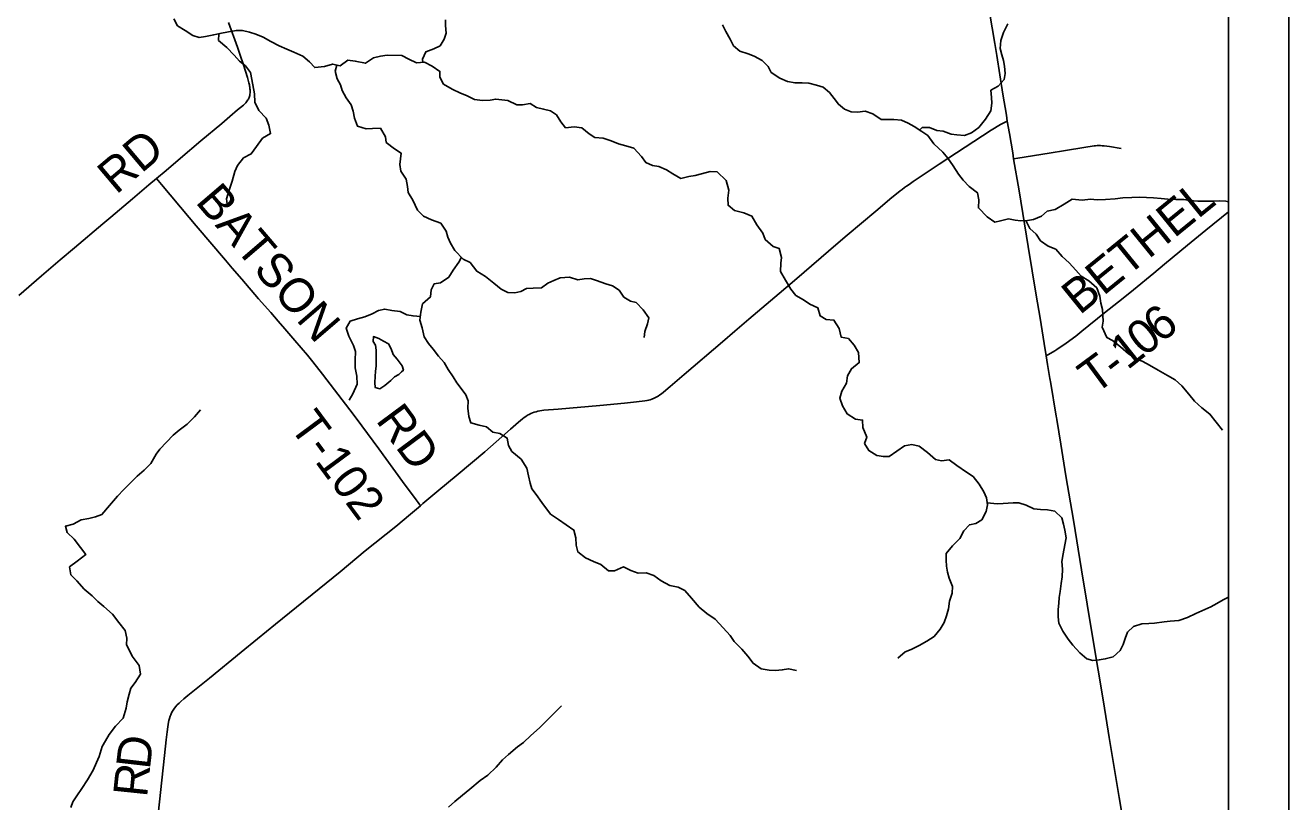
# Model space of a CAD drawing. Extents: x 0 to 34, y 0 to 22.
# Drawn here: x 6.899 to 9, y 17.368 to 18.658 of the extents above; entities that cross this region are included whole.
import ezdxf

# ---------------------------------------------------------------- set-up
doc = ezdxf.new("R2010")
doc.units = 0
for name, color, linetype in [('GM_X_County_Road', 7, 'Continuous'), ('GM_X_County_Road_Text', 7, 'Continuous'), ('GM_X_Minor_Lake', 7, 'Continuous'), ('GM_X_Minor_River', 7, 'Continuous'), ('GM_X_State_Route', 7, 'Continuous'), ('GM_X_Township_Road', 7, 'Continuous'), ('GM_X_Township_Road_Text', 7, 'Continuous'), ('SH_Data', 7, 'Continuous')]:
    doc.layers.add(name, color=color, linetype=linetype)

msp = doc.modelspace()

# ---------------------------------------------------------------- linework, layer by layer
at = {"layer": 'GM_X_County_Road'}
for points in [[(7.5558, 17.8596), (7.5602, 17.8632), (7.5833, 17.8831), (7.6187, 17.9124), (7.6628, 17.9496), (7.6914, 17.9744), (7.7058, 17.9872), (7.7188, 17.9988), (7.7255, 18.0043), (7.7283, 18.0063), (7.7311, 18.0083), (7.7341, 18.0101), (7.7366, 18.0115), (7.7394, 18.0129), (7.7423, 18.0141), (7.745, 18.0151), (7.7483, 18.016), (7.7512, 18.0167), (7.7544, 18.0174), (7.7577, 18.0179), (7.7612, 18.0184), (7.7848, 18.0204), (7.8541, 18.0265), (7.8955, 18.0305), (7.9153, 18.0325), (7.9294, 18.0342), (7.9326, 18.0346), (7.9355, 18.0352), (7.9381, 18.0358), (7.9407, 18.0368), (7.9446, 18.0384), (7.9489, 18.0407), (7.9511, 18.042), (7.9541, 18.044), (7.9567, 18.046), (7.96, 18.0485), (7.9715, 18.058), (7.9946, 18.0778), (8.0583, 18.1324), (8.079, 18.1502), (8.1022, 18.1699), (8.1523, 18.2126), (8.1822, 18.2378), (8.2466, 18.2934), (8.2656, 18.3093), (8.3132, 18.3493), (8.3401, 18.3723), (8.3507, 18.3807), (8.3537, 18.3832), (8.3571, 18.3856), (8.3611, 18.3887), (8.3642, 18.391), (8.3686, 18.394), (8.3755, 18.3988), (8.4189, 18.4276), (8.5054, 18.4839), (8.5206, 18.4937), (8.5227, 18.4948), (8.5251, 18.4959), (8.532, 18.4992)], [(7.1161, 17.3107), (7.1322, 17.4601), (7.1333, 17.4706), (7.1347, 17.4836), (7.1358, 17.4923), (7.1363, 17.4958), (7.137, 17.4997), (7.1378, 17.5028), (7.1385, 17.5058), (7.1399, 17.51), (7.1408, 17.5124), (7.1421, 17.5152), (7.1436, 17.5181), (7.1456, 17.5213), (7.1485, 17.5252), (7.1515, 17.5287), (7.1545, 17.5317), (7.1573, 17.5343), (7.1626, 17.5388), (7.1659, 17.5414), (7.1694, 17.5443), (7.2052, 17.5731), (7.2581, 17.6164), (7.2851, 17.6383), (7.3149, 17.6627), (7.4224, 17.7501), (7.4641, 17.7845), (7.5148, 17.8255), (7.5392, 17.8457), (7.5558, 17.8596)]]:
    msp.add_lwpolyline(points, dxfattribs=at)
at = {"layer": 'GM_X_Minor_Lake'}
for points in [[(7.5246, 18.0822), (7.5276, 18.085), (7.5254, 18.0926), (7.5171, 18.1034), (7.5108, 18.111), (7.5075, 18.1206), (7.5026, 18.129), (7.4947, 18.1336), (7.4868, 18.1375), (7.4777, 18.141), (7.4776, 18.1327), (7.481, 18.1266), (7.4824, 18.1186), (7.4822, 18.1015)], [(7.4822, 18.1015), (7.4821, 18.0916), (7.4812, 18.0833), (7.4807, 18.0745), (7.4802, 18.0647), (7.4809, 18.0563), (7.4885, 18.0543), (7.4969, 18.0599), (7.5069, 18.0681), (7.513, 18.0742), (7.5203, 18.0782), (7.5246, 18.0822)]]:
    msp.add_lwpolyline(points, dxfattribs=at)
at = {"layer": 'GM_X_Minor_River'}
for points in [[(7.1458, 18.6694), (7.1517, 18.6576), (7.1649, 18.6498), (7.1774, 18.6417), (7.188, 18.6382), (7.1986, 18.64), (7.2123, 18.6428), (7.2226, 18.6446), (7.2367, 18.6475), (7.25, 18.65), (7.2598, 18.6499), (7.2716, 18.6471), (7.2822, 18.6439), (7.2946, 18.6389), (7.3074, 18.6315), (7.321, 18.6245), (7.3335, 18.6187), (7.3456, 18.6136), (7.3603, 18.607)], [(7.5599, 18.5969), (7.5595, 18.602), (7.565, 18.6145), (7.5783, 18.6193), (7.5886, 18.6245), (7.5956, 18.6354), (7.5988, 18.6456), (7.5978, 18.6582), (7.5979, 18.6677)], [(8.0582, 18.659), (8.0638, 18.6479), (8.0712, 18.6353), (8.0764, 18.6246), (8.0869, 18.6157), (8.1009, 18.611), (8.1111, 18.6071), (8.1243, 18.5997), (8.1345, 18.5897), (8.1393, 18.5802), (8.1536, 18.5705), (8.1664, 18.565), (8.1789, 18.5626), (8.1907, 18.5629), (8.2021, 18.5624), (8.2149, 18.5592), (8.2259, 18.5556), (8.2361, 18.5468), (8.2439, 18.5368), (8.251, 18.5272), (8.2612, 18.5188), (8.2725, 18.5144), (8.2827, 18.5143), (8.2957, 18.5157), (8.3081, 18.511), (8.3224, 18.5017), (8.3319, 18.5016), (8.3433, 18.5019), (8.3558, 18.501), (8.3672, 18.4959), (8.377, 18.4901), (8.3898, 18.4819), (8.3996, 18.475), (8.4096, 18.4612), (8.4247, 18.4474), (8.4333, 18.4374), (8.4422, 18.4247), (8.4508, 18.411), (8.4583, 18.401), (8.4684, 18.3906), (8.4823, 18.3802), (8.4845, 18.3684), (8.4839, 18.3548), (8.4985, 18.3398), (8.5113, 18.3313), (8.5209, 18.3334)], [(8.3859, 18.4844), (8.3906, 18.4888), (8.4024, 18.4886), (8.4148, 18.4836), (8.4251, 18.4823), (8.4387, 18.4772), (8.4482, 18.4763), (8.4607, 18.4754), (8.4725, 18.4799), (8.4844, 18.4888), (8.4955, 18.5024), (8.5048, 18.5163), (8.5065, 18.5289), (8.5055, 18.5387), (8.5045, 18.5505), (8.5167, 18.5572), (8.5267, 18.5681), (8.5283, 18.5784), (8.5273, 18.5905), (8.5256, 18.6), (8.523, 18.6096), (8.5201, 18.6199), (8.521, 18.6332), (8.5257, 18.6464), (8.5331, 18.6607)], [(7.2207, 18.6443), (7.2202, 18.6333), (7.2341, 18.6213), (7.2464, 18.609), (7.2551, 18.599), (7.2652, 18.591), (7.2734, 18.5798), (7.277, 18.5593), (7.2798, 18.5448), (7.2808, 18.5308), (7.2871, 18.517), (7.2995, 18.5043), (7.3039, 18.4925), (7.3068, 18.4784), (7.2934, 18.471), (7.2833, 18.457), (7.2745, 18.4446), (7.2619, 18.4379), (7.2518, 18.4255), (7.2475, 18.4153), (7.2428, 18.3994), (7.2377, 18.3846), (7.2333, 18.3699), (7.2351, 18.3565)], [(7.3603, 18.607), (7.3716, 18.5977), (7.3802, 18.5881), (7.3962, 18.5898), (7.4099, 18.5939), (7.4224, 18.5911), (7.4354, 18.6004), (7.4475, 18.5991), (7.4645, 18.5955), (7.4779, 18.6045), (7.4897, 18.6074), (7.5008, 18.6088), (7.5251, 18.6085), (7.5367, 18.6019), (7.5492, 18.5961), (7.5625, 18.597), (7.5753, 18.5904), (7.5885, 18.5819), (7.588, 18.5721), (7.5943, 18.5606), (7.609, 18.5524), (7.6226, 18.5455), (7.6328, 18.5415), (7.646, 18.5349), (7.6593, 18.5333), (7.6718, 18.5339), (7.6813, 18.5357), (7.6916, 18.5348), (7.7011, 18.5335), (7.7162, 18.5261), (7.7256, 18.526), (7.7382, 18.5282), (7.7491, 18.522), (7.7609, 18.5192), (7.7722, 18.5164), (7.782, 18.5094), (7.7895, 18.498), (7.7973, 18.488), (7.8114, 18.4897), (7.8243, 18.4881), (7.8363, 18.478), (7.8461, 18.4719), (7.8597, 18.4709), (7.873, 18.4666), (7.8854, 18.4615), (7.8975, 18.4583), (7.9108, 18.454), (7.9235, 18.4402), (7.9306, 18.4306), (7.9419, 18.4256), (7.9526, 18.4239), (7.965, 18.4181), (7.9759, 18.4115), (7.9888, 18.4037), (8.0025, 18.407), (8.0131, 18.4088), (8.0234, 18.4117), (8.0379, 18.4153), (8.0492, 18.4148), (8.0643, 18.4002), (8.0686, 18.3846), (8.0673, 18.3709), (8.0676, 18.3592), (8.0781, 18.3503), (8.094, 18.3467), (8.1072, 18.3412), (8.1154, 18.3267), (8.1255, 18.3129), (8.1291, 18.3026), (8.1427, 18.2907), (8.1525, 18.2875), (8.1565, 18.2727), (8.1552, 18.2632), (8.1547, 18.2491), (8.1629, 18.2346), (8.1718, 18.2197), (8.1804, 18.2093), (8.1932, 18.202), (8.2038, 18.195), (8.217, 18.1888), (8.2206, 18.1754), (8.2308, 18.1692), (8.2437, 18.1683), (8.2523, 18.1542), (8.2555, 18.1401), (8.2676, 18.1377), (8.2774, 18.1265), (8.2844, 18.1143), (8.2857, 18.0976), (8.2731, 18.0875), (8.2661, 18.0758), (8.2645, 18.0636), (8.2567, 18.0504), (8.2535, 18.0387), (8.2579, 18.0257), (8.2658, 18.0123), (8.2793, 18.0034), (8.2914, 18.0022), (8.2917, 17.99), (8.2983, 17.974), (8.2944, 17.963)], [(7.4167, 18.5923), (7.4139, 18.5824), (7.4175, 18.5695), (7.4231, 18.5595), (7.4257, 18.55), (7.4324, 18.5381), (7.4406, 18.5263), (7.4439, 18.5156), (7.4464, 18.5038), (7.4512, 18.4908), (7.4655, 18.4861), (7.4762, 18.4867), (7.4895, 18.4877), (7.498, 18.4732), (7.4987, 18.4637), (7.5126, 18.4529), (7.5239, 18.4459), (7.5218, 18.4273), (7.5231, 18.4159), (7.5325, 18.4025), (7.5346, 18.3907), (7.5356, 18.3804), (7.5431, 18.3678), (7.5512, 18.351), (7.561, 18.3414), (7.5742, 18.3348), (7.5897, 18.3293), (7.5986, 18.3163), (7.6016, 18.3064), (7.606, 18.2961), (7.6134, 18.2842), (7.6269, 18.2696), (7.6386, 18.2642), (7.6495, 18.2496), (7.6642, 18.2407), (7.6781, 18.2299), (7.6901, 18.2199), (7.7014, 18.2144), (7.7132, 18.2139), (7.7231, 18.2157), (7.7326, 18.2209), (7.7433, 18.2216), (7.7573, 18.2222), (7.7677, 18.2296), (7.7776, 18.2341), (7.7886, 18.2389), (7.8038, 18.2395), (7.8175, 18.2355), (7.8285, 18.2369), (7.8387, 18.2376), (7.849, 18.2344), (7.8644, 18.2289), (7.8754, 18.2254), (7.8863, 18.2184), (7.8942, 18.2065), (7.9051, 18.1999), (7.9149, 18.1976), (7.9266, 18.1853), (7.9359, 18.1722), (7.9335, 18.1624), (7.9292, 18.1495), (7.9283, 18.1393)], [(8.5209, 18.3334), (8.5342, 18.3367), (8.5448, 18.3347), (8.5546, 18.3334), (8.5657, 18.3341), (8.5755, 18.3355), (8.5889, 18.3414), (8.5985, 18.3493), (8.6118, 18.3525), (8.6263, 18.3611), (8.6401, 18.3693), (8.6564, 18.368), (8.6701, 18.3693), (8.6815, 18.3684), (8.6951, 18.369), (8.7111, 18.37), (8.724, 18.3717), (8.7388, 18.3723), (8.7521, 18.3726), (8.7635, 18.3724), (8.7749, 18.3719), (8.7878, 18.3703), (8.7991, 18.3694), (8.8124, 18.3688), (8.8257, 18.3687), (8.8352, 18.3674), (8.8488, 18.3661), (8.8621, 18.366), (8.8747, 18.3662), (8.8845, 18.3665), (8.8955, 18.366), (8.9, 18.3652)], [(8.5627, 18.3339), (8.5697, 18.3207), (8.5802, 18.3111), (8.5869, 18.3004), (8.5997, 18.2911), (8.6125, 18.2864), (8.623, 18.2741), (8.635, 18.2634), (8.6459, 18.2515), (8.6549, 18.2415), (8.6677, 18.2334), (8.6809, 18.2218), (8.686, 18.2081), (8.6874, 18.1963), (8.6903, 18.186), (8.6916, 18.1666), (8.69, 18.1567), (8.6973, 18.1392), (8.7071, 18.1345), (8.7203, 18.1241), (8.7335, 18.1122), (8.7448, 18.1052), (8.7572, 18.0994), (8.7685, 18.0932), (8.7829, 18.0854), (8.7983, 18.0765), (8.8111, 18.0691), (8.822, 18.0591), (8.834, 18.0453), (8.8434, 18.0334), (8.8557, 18.0223), (8.8689, 18.0122), (8.8899, 17.9854)], [(7.624, 18.2728), (7.6197, 18.2644), (7.6104, 18.2512), (7.6034, 18.2399), (7.5896, 18.2305), (7.5786, 18.2284), (7.5739, 18.2186), (7.5727, 18.2068), (7.5596, 18.1952), (7.5568, 18.1815), (7.5551, 18.1683), (7.5591, 18.1557), (7.562, 18.1408), (7.5691, 18.1297), (7.5773, 18.1201), (7.5859, 18.1083), (7.5957, 18.0979), (7.6023, 18.0864), (7.6106, 18.0742), (7.6165, 18.0642), (7.6236, 18.0546), (7.6315, 18.0443), (7.6351, 18.0344), (7.635, 18.0218), (7.6363, 18.0082), (7.6396, 17.9975), (7.6536, 17.9935), (7.6657, 17.9907), (7.6766, 17.9819), (7.688, 17.9798), (7.7004, 17.9721), (7.7026, 17.9599), (7.7081, 17.95), (7.7237, 17.9369)], [(7.5559, 18.1744), (7.5438, 18.1752), (7.5336, 18.1769), (7.5223, 18.1827), (7.5086, 18.1844), (7.4965, 18.1868), (7.4862, 18.1846), (7.4755, 18.1787), (7.4637, 18.1739), (7.4515, 18.1702), (7.4389, 18.1665), (7.4327, 18.1548), (7.4371, 18.1419), (7.4445, 18.1262), (7.4482, 18.1163), (7.4473, 18.1015), (7.4475, 18.089), (7.45, 18.0749), (7.4506, 18.062), (7.4436, 18.0457), (7.4374, 18.0351)], [(7.1163, 17.9455), (7.1225, 17.9537), (7.1336, 17.9657), (7.1448, 17.9769), (7.1547, 17.9856), (7.1678, 17.9953), (7.1804, 18.0073), (7.1904, 18.0193)], [(7.0158, 17.8413), (7.0262, 17.845), (7.0389, 17.8604), (7.052, 17.8754), (7.0628, 17.887), (7.0724, 17.8968), (7.0847, 17.9088), (7.0963, 17.9189), (7.1078, 17.9301), (7.1163, 17.9455)], [(8.2944, 17.963), (8.3018, 17.9515), (8.315, 17.9434), (8.326, 17.9414), (8.3355, 17.9416), (8.3481, 17.9502), (8.3612, 17.9592), (8.3733, 17.9613), (8.3854, 17.9589), (8.3994, 17.9481), (8.4125, 17.9366), (8.4224, 17.9346), (8.4353, 17.9359), (8.4481, 17.9267)], [(7.7237, 17.9369), (7.7329, 17.922), (7.7358, 17.9095), (7.7383, 17.8973), (7.7412, 17.8878), (7.7483, 17.8782), (7.7576, 17.8651), (7.7725, 17.846), (7.7853, 17.8367), (7.7981, 17.8282), (7.8109, 17.8193), (7.8145, 17.8063), (7.8147, 17.7942), (7.818, 17.7831), (7.8304, 17.7731), (7.8436, 17.7669), (7.8561, 17.7618), (7.8689, 17.7517), (7.8787, 17.7516), (7.8936, 17.7579), (7.9061, 17.752), (7.9182, 17.7477), (7.9311, 17.7483), (7.9443, 17.7439), (7.9564, 17.7347), (7.9707, 17.7269), (7.9847, 17.7244), (7.9957, 17.7186), (8.0069, 17.7063), (8.0196, 17.6913), (8.032, 17.6805), (8.0459, 17.6712), (8.0594, 17.6566), (8.071, 17.644), (8.0777, 17.634), (8.0904, 17.6213), (8.1002, 17.6094), (8.1091, 17.5979), (8.1227, 17.5886), (8.1359, 17.5866), (8.1462, 17.5857), (8.1576, 17.5867), (8.1679, 17.5888), (8.1815, 17.586)], [(8.4481, 17.9267), (8.464, 17.9156), (8.4753, 17.9082), (8.4853, 17.8956), (8.4928, 17.883), (8.4972, 17.8727), (8.4993, 17.8612), (8.4969, 17.8499), (8.4895, 17.8363), (8.4799, 17.8304), (8.4689, 17.8282), (8.4596, 17.8181), (8.453, 17.8053), (8.441, 17.7933), (8.4302, 17.7805), (8.4301, 17.7695), (8.4307, 17.7593), (8.4325, 17.7494), (8.4354, 17.7391), (8.4409, 17.7253), (8.44, 17.7143), (8.436, 17.7011), (8.4339, 17.6882), (8.4307, 17.6765), (8.4272, 17.6655), (8.4202, 17.6546), (8.4102, 17.6426), (8.3983, 17.6348), (8.3856, 17.6274), (8.3723, 17.6207), (8.3619, 17.6167), (8.3497, 17.6066)], [(8.4987, 17.8645), (8.5149, 17.8629), (8.5252, 17.8636), (8.5415, 17.8645), (8.551, 17.8647), (8.5635, 17.8608), (8.5763, 17.8545), (8.5869, 17.8533), (8.5987, 17.8527), (8.6112, 17.8507), (8.6228, 17.8395), (8.6254, 17.8292), (8.6279, 17.8193), (8.63, 17.8064), (8.6276, 17.795), (8.6247, 17.7799), (8.6226, 17.767), (8.6236, 17.7545), (8.6234, 17.7416), (8.6218, 17.7302), (8.6197, 17.7173), (8.6184, 17.7071), (8.6175, 17.6976), (8.6166, 17.687), (8.6165, 17.6752), (8.6174, 17.6646), (8.6241, 17.6512), (8.633, 17.6382), (8.6409, 17.6282), (8.6525, 17.6152), (8.6645, 17.6055), (8.6743, 17.6027), (8.685, 17.6034), (8.6949, 17.6051), (8.7082, 17.6088), (8.7194, 17.6189), (8.7248, 17.629), (8.728, 17.6389), (8.732, 17.6498), (8.742, 17.6588), (8.7557, 17.6636), (8.7671, 17.6642), (8.7766, 17.6648), (8.7926, 17.6669), (8.8028, 17.6679), (8.8173, 17.6692), (8.8318, 17.674), (8.8456, 17.6806), (8.8704, 17.6917), (8.8803, 17.6972), (8.8907, 17.7032), (8.9, 17.708)], [(6.9744, 17.3579), (6.9779, 17.3677), (6.9845, 17.3775), (6.9927, 17.3899), (7.0024, 17.4038), (7.0117, 17.42), (7.0172, 17.4329), (7.0219, 17.4427), (7.0267, 17.4593), (7.0321, 17.4691), (7.0383, 17.4797), (7.0488, 17.4932), (7.0615, 17.5067), (7.0666, 17.523), (7.0683, 17.5339), (7.0715, 17.5464), (7.0743, 17.5563), (7.0816, 17.566), (7.0902, 17.58), (7.0881, 17.5944), (7.0765, 17.6094), (7.0721, 17.6189), (7.0673, 17.6285), (7.0678, 17.6395), (7.065, 17.6524), (7.0545, 17.6658), (7.0441, 17.6796), (7.0294, 17.6924), (7.0196, 17.7005), (7.0099, 17.7101), (6.9968, 17.7213), (6.9844, 17.7351), (6.9747, 17.7447), (6.9722, 17.758), (6.9852, 17.7677), (6.9994, 17.7785), (6.9909, 17.7904), (6.98, 17.8042), (6.9684, 17.815), (6.9655, 17.8257), (6.9785, 17.8293), (6.9915, 17.8363), (7.0044, 17.8388), (7.0158, 17.8413)], [(7.6026, 17.3589), (7.613, 17.3678), (7.6261, 17.3787), (7.638, 17.3884), (7.6553, 17.403), (7.6679, 17.4119), (7.6818, 17.4254), (7.6926, 17.4374), (7.7026, 17.4464), (7.7175, 17.4587), (7.7271, 17.4662), (7.7398, 17.4778), (7.7537, 17.4905), (7.7633, 17.4999), (7.7776, 17.5145), (7.7906, 17.5269)]]:
    msp.add_lwpolyline(points, dxfattribs=at)
at = {"layer": 'GM_X_State_Route'}
msp.add_lwpolyline([(8.7345, 17.2755), (8.7178, 17.3748), (8.7014, 17.4747), (8.6919, 17.5336), (8.6743, 17.639), (8.6553, 17.7531), (8.6418, 17.8358), (8.6295, 17.9094), (8.621, 17.9621), (8.6143, 18.0032), (8.6138, 18.0062), (8.6134, 18.0087), (8.6038, 18.0662), (8.6033, 18.0687), (8.6029, 18.0711), (8.599, 18.0944), (8.5966, 18.1089), (8.5932, 18.1294), (8.5864, 18.1717), (8.5801, 18.2097), (8.5669, 18.2906), (8.5515, 18.3832), (8.5425, 18.4365), (8.5409, 18.4463), (8.5355, 18.4787), (8.532, 18.4992), (8.5304, 18.5088), (8.5248, 18.5437), (8.5145, 18.6082), (8.5112, 18.6284), (8.4985, 18.7037)], dxfattribs=at)
at = {"layer": 'GM_X_Township_Road'}
for points in [[(8.9, 16.5763), (8.9, 19.1426), (8.4186, 19.1875), (7.8888, 19.2268), (7.1834, 19.2978), (6.3561, 19.3959), (5.8809, 19.4409), (5.6889, 19.4592), (5.1411, 19.5203), (4.4849, 19.6021), (4.4789, 19.5742), (4.3389, 18.9527), (4.2897, 18.7747), (4.1943, 18.4289), (4.1901, 18.4135), (4.0744, 17.9948), (3.9903, 17.6899), (3.7921, 17.074)], [(7.1171, 18.4037), (7.133, 18.4171), (7.157, 18.4378), (7.1906, 18.4663), (7.2254, 18.4953), (7.2392, 18.5069), (7.252, 18.5177), (7.2617, 18.5255), (7.2644, 18.5282), (7.2658, 18.5297), (7.2669, 18.5311), (7.268, 18.5327), (7.269, 18.5343), (7.2698, 18.5357), (7.2705, 18.5371), (7.271, 18.5386), (7.2716, 18.5401), (7.272, 18.542), (7.2725, 18.5439), (7.2726, 18.546), (7.2728, 18.5477), (7.2728, 18.5494), (7.2728, 18.5509), (7.2725, 18.5529), (7.2723, 18.5547), (7.2722, 18.5559), (7.2719, 18.5574), (7.2715, 18.5594), (7.271, 18.5614), (7.2708, 18.5627), (7.2682, 18.5717), (7.2617, 18.5925), (7.2561, 18.6089), (7.2517, 18.6219), (7.237, 18.6629)], [(8.5425, 18.4365), (8.5496, 18.4375), (8.6017, 18.4459), (8.6286, 18.4503), (8.6593, 18.4553), (8.6765, 18.4579), (8.6789, 18.4582), (8.6814, 18.4584), (8.6841, 18.4585), (8.687, 18.4584), (8.69, 18.4582), (8.6932, 18.4581), (8.7018, 18.4569), (8.7216, 18.4539)], [(6.8879, 18.2095), (6.9258, 18.2417), (6.9569, 18.2685), (6.9806, 18.2885), (7.0276, 18.3282), (7.0409, 18.3394), (7.0769, 18.37), (7.1044, 18.3931), (7.1171, 18.4037)], [(7.5558, 17.8596), (7.552, 17.865), (7.5487, 17.8696), (7.5262, 17.9001), (7.4866, 17.9542), (7.4583, 17.9928), (7.4443, 18.0118), (7.4257, 18.036), (7.3932, 18.0783), (7.3772, 18.0989), (7.3681, 18.11), (7.3473, 18.1347), (7.3305, 18.1538), (7.3196, 18.1666), (7.3071, 18.1812), (7.2867, 18.2039), (7.2588, 18.2364), (7.2431, 18.2548), (7.2319, 18.2681), (7.1831, 18.3252), (7.1715, 18.3391), (7.1255, 18.3937), (7.1171, 18.4037)], [(8.5966, 18.1089), (8.6034, 18.1127), (8.6083, 18.1154), (8.6111, 18.1172), (8.6145, 18.1195), (8.6298, 18.1302), (8.6458, 18.1419), (8.6561, 18.1499), (8.6938, 18.1804), (8.7244, 18.2047), (8.7419, 18.2187), (8.7754, 18.2464), (8.7934, 18.2616), (8.8318, 18.2932), (8.8621, 18.3179), (8.9, 18.3486)]]:
    msp.add_lwpolyline(points, dxfattribs=at)
at = {"layer": 'SH_Data'}
for p, q in [((9, 21), (9, 14)), ((8.9, 20.9), (8.9, 14.1))]:
    msp.add_line(p, q, dxfattribs=at)

# ---------------------------------------------------------------- texts
at = {"layer": 'GM_X_County_Road_Text'}
for s, rotation, p in [('D', 83.4285, (7.106, 17.4202)), ('R', 84.0645, (7.1012, 17.3739))]:
    msp.add_text(s, height=0.0568, rotation=rotation, dxfattribs=at).set_placement(p)
at = {"layer": 'GM_X_Township_Road_Text'}
for s, height, rotation, p in [('RD', 0.05682, 40.179, (7.0499, 18.376)), ('BATSON', 0.05682, 310.5816, (7.1804, 18.3644)), ('BETHEL', 0.05682, 39.1033, (8.6523, 18.1758)), ('6', 0.0568, 39.3747, (8.7873, 18.1286)), ('0', 0.0568, 38.556, (8.7593, 18.1062)), ('1', 0.0568, 38.4111, (8.7317, 18.0844)), ('T', 0.0568, 36.3882, (8.6773, 18.0436)), ('-', 0.0568, 37.6307, (8.7126, 18.0696)), ('RD', 0.05682, 306.5736, (7.4805, 18.0016)), ('T-102', 0.05682, 306.5377, (7.3366, 17.9913))]:
    msp.add_text(s, height=height, rotation=rotation, dxfattribs=at).set_placement(p)

doc.saveas('drawing.dxf')
